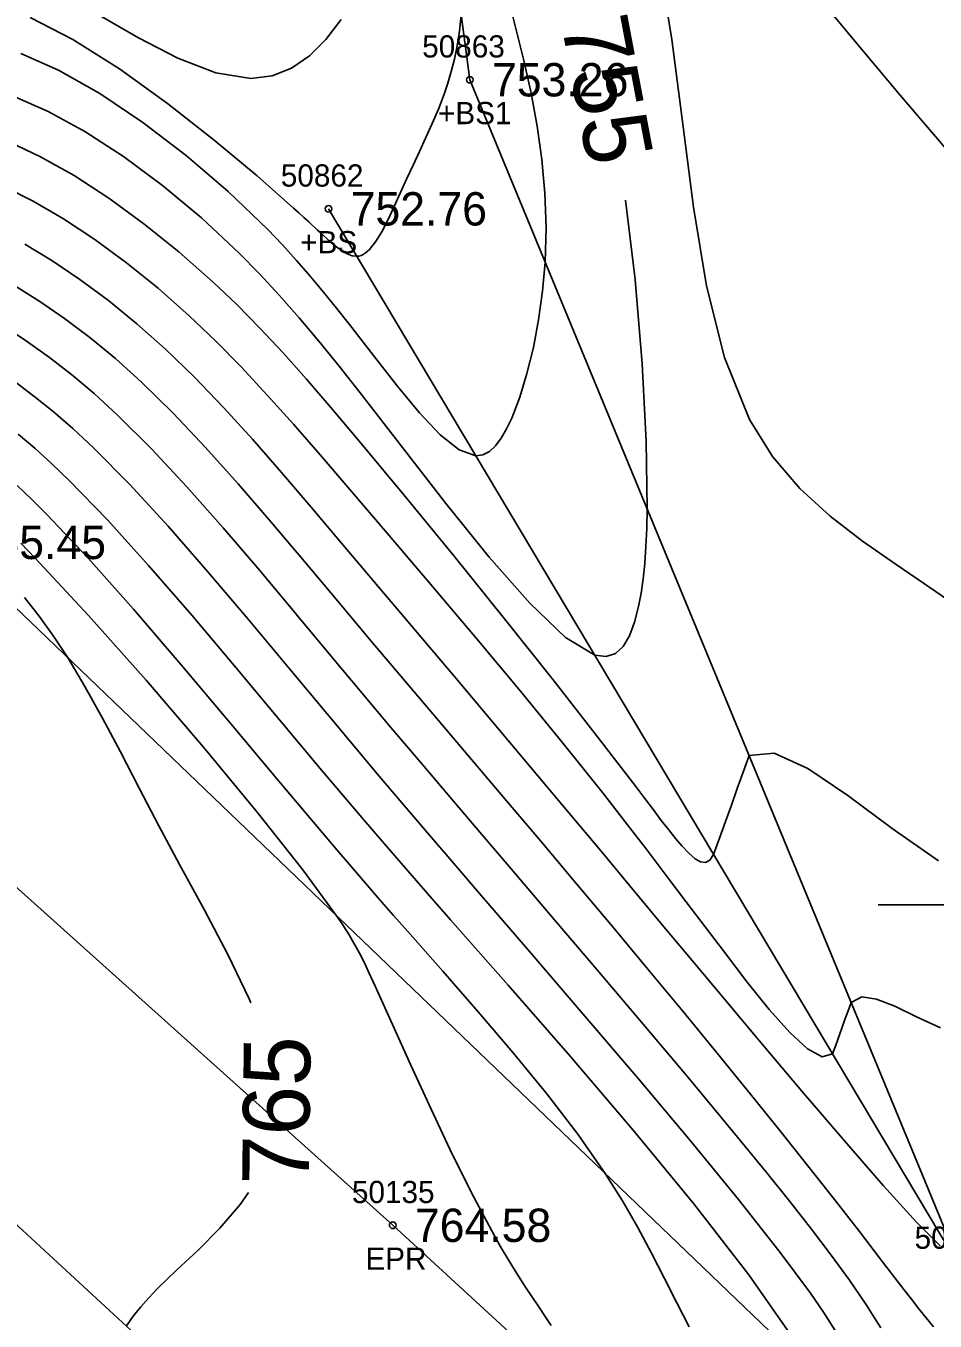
# Model space of a CAD drawing. Extents: x 1378535 to 1380697, y 997729 to 1000024.
# Drawn here: x 1379057.9 to 1379098.8, y 999524.5 to 999582.8 of the extents above; entities that cross this region are included whole.
import ezdxf

# ---------------------------------------------------------------- set-up
doc = ezdxf.new("R2010")
doc.units = 0
for name, color, linetype in [('RD_DTM_BkLn1', 7, 'Continuous'), ('RD_DTM_BkLn2', 7, 'Continuous'), ('RD_DTM_BkLn_txCode', 7, 'Continuous'), ('RD_DTM_Major1', 7, 'Continuous'), ('RD_DTM_Major1_Lbl', 7, 'Continuous'), ('RD_DTM_Minor1', 7, 'Continuous'), ('RD_EX_Misc', 7, 'Continuous'), ('RD_EX_Road', 7, 'Continuous'), ('RD_EX_Road_txCode', 7, 'Continuous'), ('RD_EX_TX_Misc_ELEV', 7, 'Continuous'), ('RD_EX_TX_Road_ELEV', 7, 'Continuous'), ('RD_SMD_Locator', 7, 'Continuous')]:
    doc.layers.add(name, color=color, linetype=linetype)

msp = doc.modelspace()

# ---------------------------------------------------------------- linework, layer by layer
at = {"layer": 'RD_DTM_BkLn1'}
msp.add_lwpolyline([(1379201.7, 999398.205), (1379156.533, 999438.891), (1379112.084, 999479.847), (1379066.495, 999520.561), (1379020.821, 999562.613), (1378974.239, 999604.981), (1378928.957, 999646.778), (1378882.739, 999688.619), (1378834.578, 999733.071), (1378787.698, 999775.121), (1378743.642, 999816.274), (1378698.706, 999856.431), (1378652.056, 999898.787), (1378607.023, 999939.646), (1378604.538, 999941.267)], dxfattribs=at)
at = {"layer": 'RD_DTM_BkLn2'}
for points in [[(1379093.966, 999521.58), (1379054.373, 999559.565), (1379010.103, 999595.197), (1378968.034, 999632.397), (1378925.231, 999671.641)], [(1379071.515, 999574.573), (1379100.033, 999526.783), (1379077.877, 999580.381), (1379073.528, 999613.162), (1379081.321, 999644.423)]]:
    msp.add_lwpolyline(points, dxfattribs=at)
at = {"layer": 'RD_DTM_Major1'}
for points in [[(1379057.373, 999579.632), (1379058.908, 999578.959), (1379060.562, 999578.046), (1379062.292, 999576.921), (1379064.053, 999575.616), (1379065.802, 999574.161), (1379067.495, 999572.585), (1379068.41, 999571.655), (1379069.305, 999570.688), (1379070.194, 999569.676), (1379071.088, 999568.612), (1379072.001, 999567.487), (1379072.945, 999566.292), (1379074.845, 999563.838), (1379076.812, 999561.307), (1379078.752, 999558.904), (1379080.574, 999556.831), (1379082.186, 999555.294), (1379083.496, 999554.495), (1379084.009, 999554.428), (1379084.435, 999554.567), (1379084.785, 999554.887), (1379085.067, 999555.363), (1379085.294, 999555.97), (1379085.474, 999556.681), (1379085.585, 999557.276), (1379085.676, 999557.921), (1379085.748, 999558.62), (1379085.802, 999559.375), (1379085.838, 999560.193), (1379085.858, 999561.075), (1379085.82, 999564.11), (1379085.64, 999567.604), (1379085.314, 999571.39), (1379084.883, 999574.966)], [(1379057.019, 999569.227), (1379057.982, 999568.589), (1379058.958, 999567.89), (1379059.953, 999567.118), (1379060.975, 999566.258), (1379062.028, 999565.297), (1379063.562, 999563.768), (1379065.152, 999562.059), (1379066.779, 999560.219), (1379068.425, 999558.294), (1379070.071, 999556.332), (1379071.699, 999554.379), (1379073.02, 999552.8), (1379074.33, 999551.243), (1379075.643, 999549.689), (1379076.973, 999548.121), (1379078.333, 999546.522), (1379079.737, 999544.874), (1379081.679, 999542.596), (1379083.676, 999540.25), (1379085.678, 999537.889), (1379087.637, 999535.561), (1379089.507, 999533.316), (1379091.237, 999531.205), (1379092.284, 999529.904), (1379093.252, 999528.672), (1379094.143, 999527.499), (1379094.959, 999526.374), (1379095.703, 999525.287), (1379096.377, 999524.226)], [(1379057.845, 999557.083), (1379058.504, 999556.25), (1379059.152, 999555.35), (1379059.799, 999554.359), (1379060.562, 999553.078), (1379061.347, 999551.663), (1379062.16, 999550.135), (1379063.006, 999548.513), (1379063.892, 999546.819), (1379064.822, 999545.072), (1379065.923, 999543.053), (1379066.997, 999541.026), (1379067.954, 999539.024), (1379068.023, 999538.847)], [(1379067.92, 999530.317), (1379067.545, 999529.77), (1379066.628, 999528.711), (1379065.65, 999527.729), (1379064.683, 999526.815), (1379064.245, 999526.399), (1379063.828, 999525.99), (1379063.435, 999525.582), (1379063.069, 999525.17), (1379062.731, 999524.748), (1379062.424, 999524.31)]]:
    msp.add_lwpolyline(points, dxfattribs=at)
at = {"layer": 'RD_DTM_Minor1'}
for points in [[(1379099.869, 999556.657), (1379098.583, 999557.543), (1379097.058, 999558.565), (1379095.546, 999559.614), (1379094.089, 999560.741), (1379092.728, 999561.995), (1379091.504, 999563.428), (1379090.46, 999565.089), (1379089.332, 999567.879), (1379088.533, 999571.105), (1379087.948, 999574.647), (1379087.466, 999578.385), (1379086.971, 999582.197), (1379086.352, 999585.965)], [(1379099.714, 999576.799), (1379097.232, 999579.706), (1379095.069, 999582.286), (1379093.364, 999584.351)], [(1379057.671, 999581.557), (1379059.371, 999580.807), (1379061.224, 999579.757), (1379063.16, 999578.461), (1379065.112, 999576.973), (1379067.01, 999575.348), (1379068.787, 999573.641), (1379069.449, 999572.947), (1379070.086, 999572.247), (1379070.701, 999571.541), (1379071.299, 999570.828), (1379071.885, 999570.107), (1379072.462, 999569.376), (1379073.549, 999567.969), (1379074.605, 999566.613), (1379075.611, 999565.397), (1379076.549, 999564.408), (1379077.399, 999563.735), (1379078.143, 999563.466), (1379078.468, 999563.507), (1379078.766, 999563.659), (1379079.041, 999563.91), (1379079.296, 999564.251), (1379079.536, 999564.671), (1379079.764, 999565.159), (1379080.122, 999566.097), (1379080.449, 999567.165), (1379080.736, 999568.336), (1379080.974, 999569.58), (1379081.154, 999570.87), (1379081.268, 999572.177), (1379081.31, 999573.732), (1379081.255, 999575.271), (1379081.116, 999576.791), (1379080.904, 999578.294), (1379080.631, 999579.779), (1379080.308, 999581.246), (1379080.043, 999582.326), (1379079.765, 999583.41)], [(1379058.09, 999583.178), (1379060.014, 999582.197), (1379062.115, 999580.865), (1379064.276, 999579.31), (1379066.379, 999577.663), (1379068.308, 999576.053), (1379069.945, 999574.608), (1379070.183, 999574.391), (1379070.411, 999574.182), (1379070.627, 999573.983), (1379071.028, 999573.612), (1379071.213, 999573.443), (1379071.541, 999573.149), (1379071.837, 999572.9), (1379072.106, 999572.699), (1379072.352, 999572.552), (1379072.578, 999572.463), (1379072.789, 999572.438), (1379072.889, 999572.45), (1379072.986, 999572.478), (1379073.081, 999572.522), (1379073.175, 999572.58), (1379073.266, 999572.652), (1379073.357, 999572.737), (1379073.639, 999573.083), (1379073.915, 999573.532), (1379074.19, 999574.06), (1379074.466, 999574.647), (1379074.746, 999575.271), (1379075.034, 999575.912), (1379075.322, 999576.531), (1379075.614, 999577.15), (1379075.906, 999577.775), (1379076.191, 999578.411), (1379076.465, 999579.063), (1379076.721, 999579.738), (1379076.889, 999580.233), (1379077.044, 999580.754), (1379077.183, 999581.31), (1379077.305, 999581.912), (1379077.408, 999582.573), (1379077.489, 999583.302)], [(1379061.202, 999583.279), (1379062.968, 999582.265), (1379064.74, 999581.351), (1379066.449, 999580.689), (1379068.028, 999580.434), (1379068.981, 999580.555), (1379069.856, 999580.904), (1379070.66, 999581.458), (1379071.404, 999582.193), (1379072.095, 999583.086)], [(1379057.151, 999577.585), (1379058.566, 999576.919), (1379060.068, 999576.069), (1379061.628, 999575.056), (1379063.212, 999573.905), (1379064.79, 999572.638), (1379066.33, 999571.279), (1379067.389, 999570.265), (1379068.431, 999569.205), (1379069.472, 999568.088), (1379070.53, 999566.904), (1379071.621, 999565.642), (1379072.765, 999564.291), (1379074.91, 999561.71), (1379077.167, 999558.948), (1379079.438, 999556.13), (1379081.624, 999553.38), (1379083.625, 999550.823), (1379085.343, 999548.584), (1379085.754, 999548.038), (1379086.137, 999547.53), (1379086.494, 999547.06), (1379086.826, 999546.633), (1379087.133, 999546.25), (1379087.417, 999545.915), (1379087.73, 999545.579), (1379088.013, 999545.332), (1379088.265, 999545.187), (1379088.488, 999545.161), (1379088.683, 999545.269), (1379088.85, 999545.524), (1379089.116, 999546.265), (1379089.382, 999547.007), (1379089.648, 999547.749), (1379089.914, 999548.49), (1379090.18, 999549.232), (1379090.447, 999549.974), (1379091.58, 999550.079), (1379093.091, 999549.388), (1379094.888, 999548.171), (1379096.878, 999546.695), (1379098.97, 999545.232)], [(1379056.924, 999575.579), (1379058.227, 999574.92), (1379059.592, 999574.119), (1379060.999, 999573.189), (1379062.426, 999572.144), (1379063.852, 999570.997), (1379065.256, 999569.76), (1379066.437, 999568.631), (1379067.601, 999567.443), (1379068.762, 999566.194), (1379069.937, 999564.882), (1379071.14, 999563.504), (1379072.385, 999562.057), (1379074.256, 999559.873), (1379076.204, 999557.586), (1379078.184, 999555.237), (1379080.156, 999552.868), (1379082.076, 999550.519), (1379083.902, 999548.233), (1379084.874, 999546.988), (1379085.809, 999545.773), (1379086.716, 999544.582), (1379087.601, 999543.413), (1379088.47, 999542.262), (1379089.332, 999541.124), (1379090.363, 999539.781), (1379091.355, 999538.546), (1379092.272, 999537.512), (1379093.077, 999536.773), (1379093.733, 999536.422), (1379094.203, 999536.553), (1379094.342, 999536.939), (1379094.619, 999537.712), (1379094.758, 999538.099), (1379094.897, 999538.486), (1379095.036, 999538.872), (1379095.513, 999539.114), (1379096.176, 999539.022), (1379097.003, 999538.693), (1379097.97, 999538.226), (1379099.053, 999537.72)], [(1379057.85, 999572.99), (1379059.077, 999572.246), (1379060.335, 999571.4), (1379061.613, 999570.452), (1379062.9, 999569.404), (1379064.187, 999568.259), (1379065.491, 999566.993), (1379066.792, 999565.639), (1379068.095, 999564.205), (1379069.41, 999562.704), (1379070.742, 999561.145), (1379072.101, 999559.538), (1379073.758, 999557.578), (1379077.167, 999553.546), (1379078.897, 999551.497), (1379080.628, 999549.441), (1379082.35, 999547.387), (1379083.713, 999545.756), (1379085.078, 999544.117), (1379086.462, 999542.455), (1379087.88, 999540.755), (1379089.348, 999538.999), (1379090.881, 999537.171), (1379092.814, 999534.881), (1379094.732, 999532.636), (1379096.499, 999530.61), (1379097.982, 999528.977), (1379099.046, 999527.91)], [(1379057.442, 999571.098), (1379058.533, 999570.41), (1379059.646, 999569.641), (1379060.78, 999568.784), (1379061.934, 999567.832), (1379063.108, 999566.776), (1379064.535, 999565.373), (1379065.984, 999563.838), (1379067.453, 999562.198), (1379068.938, 999560.48), (1379070.435, 999558.711), (1379071.94, 999556.917), (1379073.445, 999555.129), (1379074.955, 999553.34), (1379076.472, 999551.548), (1379079.527, 999547.941), (1379081.067, 999546.119), (1379082.68, 999544.207), (1379084.292, 999542.287), (1379085.891, 999540.371), (1379087.468, 999538.469), (1379089.011, 999536.591), (1379090.509, 999534.746), (1379091.823, 999533.109), (1379093.083, 999531.522), (1379094.28, 999529.999), (1379095.405, 999528.554), (1379096.451, 999527.202), (1379097.407, 999525.955), (1379097.748, 999525.51), (1379098.079, 999525.083), (1379098.406, 999524.671), (1379098.735, 999524.274)], [(1379057.417, 999566.789), (1379058.263, 999566.152), (1379059.127, 999565.457), (1379060.018, 999564.686), (1379060.946, 999563.823), (1379062.577, 999562.172), (1379064.303, 999560.29), (1379066.089, 999558.248), (1379067.9, 999556.114), (1379069.7, 999553.958), (1379071.455, 999551.848), (1379072.592, 999550.489), (1379073.712, 999549.159), (1379074.833, 999547.835), (1379075.975, 999546.494), (1379077.156, 999545.113), (1379078.397, 999543.669), (1379080.663, 999541.037), (1379083.053, 999538.256), (1379085.467, 999535.425), (1379087.803, 999532.643), (1379089.961, 999530.008), (1379091.841, 999527.621), (1379092.554, 999526.674), (1379093.201, 999525.782), (1379093.789, 999524.932), (1379094.324, 999524.111)], [(1379057.56, 999564.431), (1379058.298, 999563.805), (1379059.06, 999563.12), (1379059.857, 999562.357), (1379061.573, 999560.584), (1379063.427, 999558.531), (1379065.369, 999556.288), (1379067.348, 999553.944), (1379069.316, 999551.588), (1379071.221, 999549.31), (1379072.165, 999548.192), (1379073.095, 999547.099), (1379074.029, 999546.011), (1379074.981, 999544.909), (1379075.97, 999543.774), (1379077.01, 999542.587), (1379079.601, 999539.64), (1379082.393, 999536.445), (1379085.231, 999533.126), (1379087.963, 999529.807), (1379090.434, 999526.613), (1379092.492, 999523.67)], [(1379057.511, 999562.123), (1379058.164, 999561.501), (1379058.848, 999560.823), (1379060.706, 999558.853), (1379062.744, 999556.562), (1379064.89, 999554.064), (1379067.071, 999551.476), (1379069.216, 999548.915), (1379071.252, 999546.495), (1379071.913, 999545.719), (1379072.557, 999544.967), (1379073.191, 999544.231), (1379073.821, 999543.506), (1379074.451, 999542.784), (1379075.086, 999542.059), (1379076.66, 999540.27), (1379078.256, 999538.444), (1379079.829, 999536.6), (1379081.336, 999534.759), (1379082.731, 999532.942), (1379083.971, 999531.169), (1379084.742, 999529.941), (1379085.431, 999528.745), (1379086.057, 999527.581), (1379086.64, 999526.448), (1379087.199, 999525.346), (1379087.752, 999524.274)], [(1379057.669, 999559.536), (1379058.326, 999558.858), (1379060.724, 999556.281), (1379063.309, 999553.372), (1379065.9, 999550.348), (1379068.314, 999547.427), (1379070.37, 999544.827), (1379071.885, 999542.764), (1379072.027, 999542.555), (1379072.159, 999542.357), (1379072.282, 999542.167), (1379072.397, 999541.985), (1379072.504, 999541.808), (1379072.606, 999541.636), (1379072.765, 999541.355), (1379072.915, 999541.077), (1379073.057, 999540.798), (1379073.197, 999540.512), (1379073.337, 999540.214), (1379073.517, 999539.824), (1379073.551, 999539.748), (1379073.586, 999539.671), (1379073.621, 999539.593), (1379073.657, 999539.514), (1379073.694, 999539.433), (1379074.397, 999537.87), (1379075.223, 999536.042), (1379076.133, 999534.063), (1379077.09, 999532.047), (1379078.054, 999530.108), (1379078.988, 999528.36), (1379079.292, 999527.83), (1379079.586, 999527.332), (1379079.872, 999526.866), (1379080.149, 999526.428), (1379080.416, 999526.018), (1379080.673, 999525.631), (1379080.984, 999525.17), (1379081.274, 999524.739), (1379081.538, 999524.333)]]:
    msp.add_lwpolyline(points, dxfattribs=at)
at = {"layer": 'RD_EX_Misc'}
msp.add_line((1379096.249, 999543.264), (1379106.249, 999543.264), dxfattribs=at)
at = {"layer": 'RD_EX_Road'}
msp.add_lwpolyline([(1379209.475, 999405.54), (1379163.997, 999446.485), (1379118.805, 999488.017), (1379074.408, 999528.841), (1379028.669, 999569.9), (1378981.979, 999612.718), (1378937.166, 999653.911), (1378890.129, 999696.785), (1378842.566, 999740.72), (1378794.879, 999783.075), (1378749.806, 999824.149), (1378706.231, 999863.66), (1378659.579, 999905.32), (1378614.058, 999947.757), (1378610.306, 999950.384)], dxfattribs=at)
at = {"layer": 'RD_SMD_Locator'}
for centre in [(1379077.877, 999580.381), (1379071.515, 999574.573), (1379074.408, 999528.841)]:
    msp.add_circle(centre, 0.15, dxfattribs=at)

# ---------------------------------------------------------------- texts
at = {"layer": 'RD_DTM_BkLn_txCode'}
for s, p in [('50863', (1379075.735, 999581.381)), ('+BS1', (1379076.444, 999578.381)), ('50862', (1379069.373, 999575.573)), ('+BS', (1379070.247, 999572.573)), ('50674', (1379097.891, 999527.783))]:
    msp.add_text(s, height=1, dxfattribs=at).set_placement(p)
at = {"layer": 'RD_DTM_Major1_Lbl'}
for s, rotation, p in [('755', 280.73112, (1379081.976, 999582.96)), ('765', 89.31279, (1379070.631, 999530.636))]:
    msp.add_text(s, height=3, rotation=rotation, dxfattribs=at).set_placement(p)
at = {"layer": 'RD_EX_Road_txCode'}
for s, p in [('50135', (1379072.573, 999529.841)), ('EPR', (1379073.18, 999526.841))]:
    msp.add_text(s, height=1, dxfattribs=at).set_placement(p)
at = {"layer": 'RD_EX_TX_Misc_ELEV'}
for s, p in [('753.26', (1379078.877, 999579.631)), ('752.76', (1379072.515, 999573.823)), ('765.45', (1379055.373, 999558.815))]:
    msp.add_text(s, height=1.5, dxfattribs=at).set_placement(p)
at = {"layer": 'RD_EX_TX_Road_ELEV'}
msp.add_text('764.58', height=1.5, dxfattribs=at).set_placement((1379075.408, 999528.091))

doc.saveas('drawing.dxf')
